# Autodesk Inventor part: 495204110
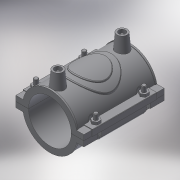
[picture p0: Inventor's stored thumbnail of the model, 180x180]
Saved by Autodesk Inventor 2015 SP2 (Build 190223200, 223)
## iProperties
Created: 2017-07
Part Number: 495204110
Material: Generic
Description: PLASSON REPAIR SADDLE 110
Document SubType Name: Modeling
Designer: KIM
Density: 1 g/cm^3
Appearance: Default
Author: KIM
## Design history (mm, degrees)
derived "495204.ipt"
feature "Solid1::495204.ipt"
tag "TaggingFeature1"
body "Solid1"
other parameters: "d1" = 132, "d2" = 148, "d3" = 27.5, "d4" = 118, "d5" = 0, "d6" = 0.1, "d8" = 0, "d19" = 6, "d20" = 6, "d21" = 70.8, "d23" = 0, "d24" = 35.4, "d26" = 0, "d27" = 3, "d28" = 3, "d29" = 3, "d30" = 36.66667, "d31" = 6, "d32" = 0, "d33" = 0, "d34" = 0.6, "d40" = 68.64, "d41" = 64.9, "d43" = 0, "d45" = 0, "d47" = 71.28, "d48" = 47.2, "d50" = 0, "d70" = 15, "d72" = 0, "d73" = 6, "d75" = 5, "d76" = 0, "d77" = 5.5, "d78" = 84, "d79" = 15, "d80" = 47.2, "d82" = 5 deg, "d84" = 4, "d85" = 14, "d86" = 0, "d87" = 3, "d88" = 0, "d89" = 1, "d90" = 1, "d91" = 94.4, "d92" = 0, "d93" = 0.5, "d94" = 57.89474, "d96" = 134.64, "d97" = 2.36, "d98" = 0, "d99" = 47.2, "d100" = 0, "d102" = 3.54, "B_" = 148, "H_" = 29, "L_" = 118, "d_t" = 6
